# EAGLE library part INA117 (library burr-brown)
Difference Amplifier High Common-Mode Voltage
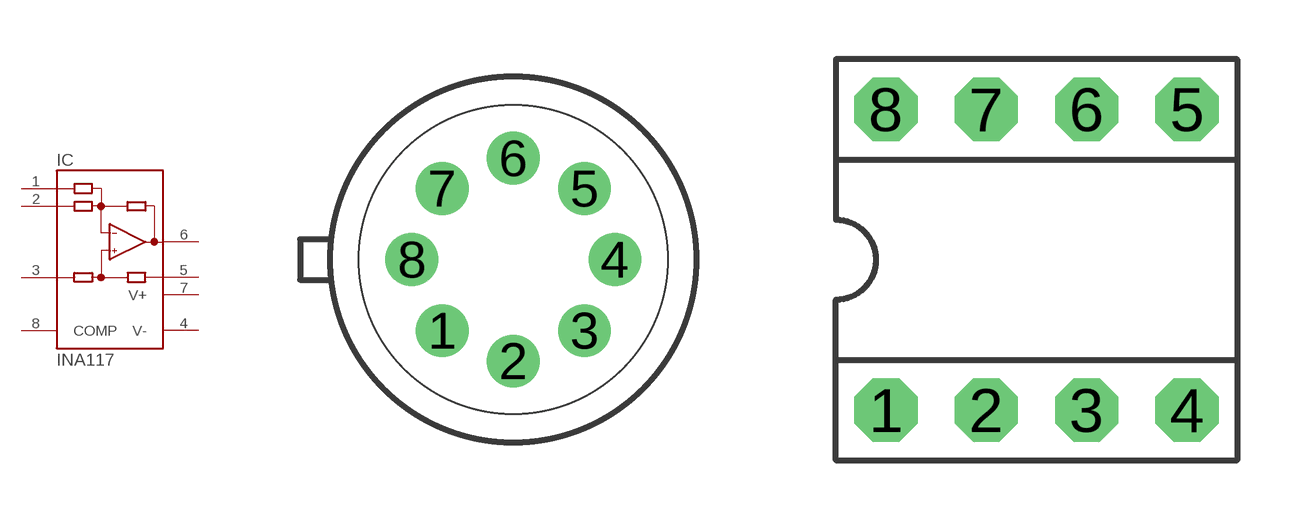
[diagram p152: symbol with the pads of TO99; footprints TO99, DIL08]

Designator prefix IC

## INA117M (MPN: INA117AM; OC_FARNELL: 1459424; OC_NEWARK: 61M6784)  [TO99]
1  REFB  in
2  -IN  in
3  +IN  in
4  V-  pwr
5  REFA  in
6  OUT  out
7  V+  pwr
8  COMP  pas

## INA117P (MF: TEXAS INSTRUMENTS; MPN: INA117P; OC_FARNELL: 1470350; OC_NEWARK: 74K3811)  [DIL08]
Pads as for TO99

## INA117U (MF: TEXAS INSTRUMENTS; MPN: INA117KU; OC_FARNELL: 1706653; OC_NEWARK: 17M6717)  [SO08]
Pads as for TO99

## Footprint TO99 (pad centres in mm)
Metal can Package
drill 0.813 round: 1 -1.778,-1.778; 2 0,-2.54; 3 1.778,-1.778; 4 2.54,0; 5 1.778,1.778; 6 0,2.54; 7 -1.778,1.778; 8 -2.54,0

## Footprint DIL08 (pad centres in mm)
Dual In Line
drill 0.813 pad 1.6 octagon: 1 -3.81,-3.81; 2 -1.27,-3.81; 3 1.27,-3.81; 4 3.81,-3.81; 5 3.81,3.81; 6 1.27,3.81; 7 -1.27,3.81; 8 -3.81,3.81

## Footprint SO08 (pad centres in mm)
Small Outline Package
smd 0.61 x 2.21: 1 -1.905,-2.616; 2 -0.635,-2.616; 3 0.635,-2.616; 4 1.905,-2.616; 5 1.905,2.616; 6 0.635,2.616; 7 -0.635,2.616; 8 -1.905,2.616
